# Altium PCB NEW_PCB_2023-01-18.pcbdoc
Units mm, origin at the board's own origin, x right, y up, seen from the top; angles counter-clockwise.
Board outline 66.65 x 67.28 mm, 2 copper layers (Top Layer, Bottom Layer); 6 components, 17 nets, 50 pads, 2 vias.
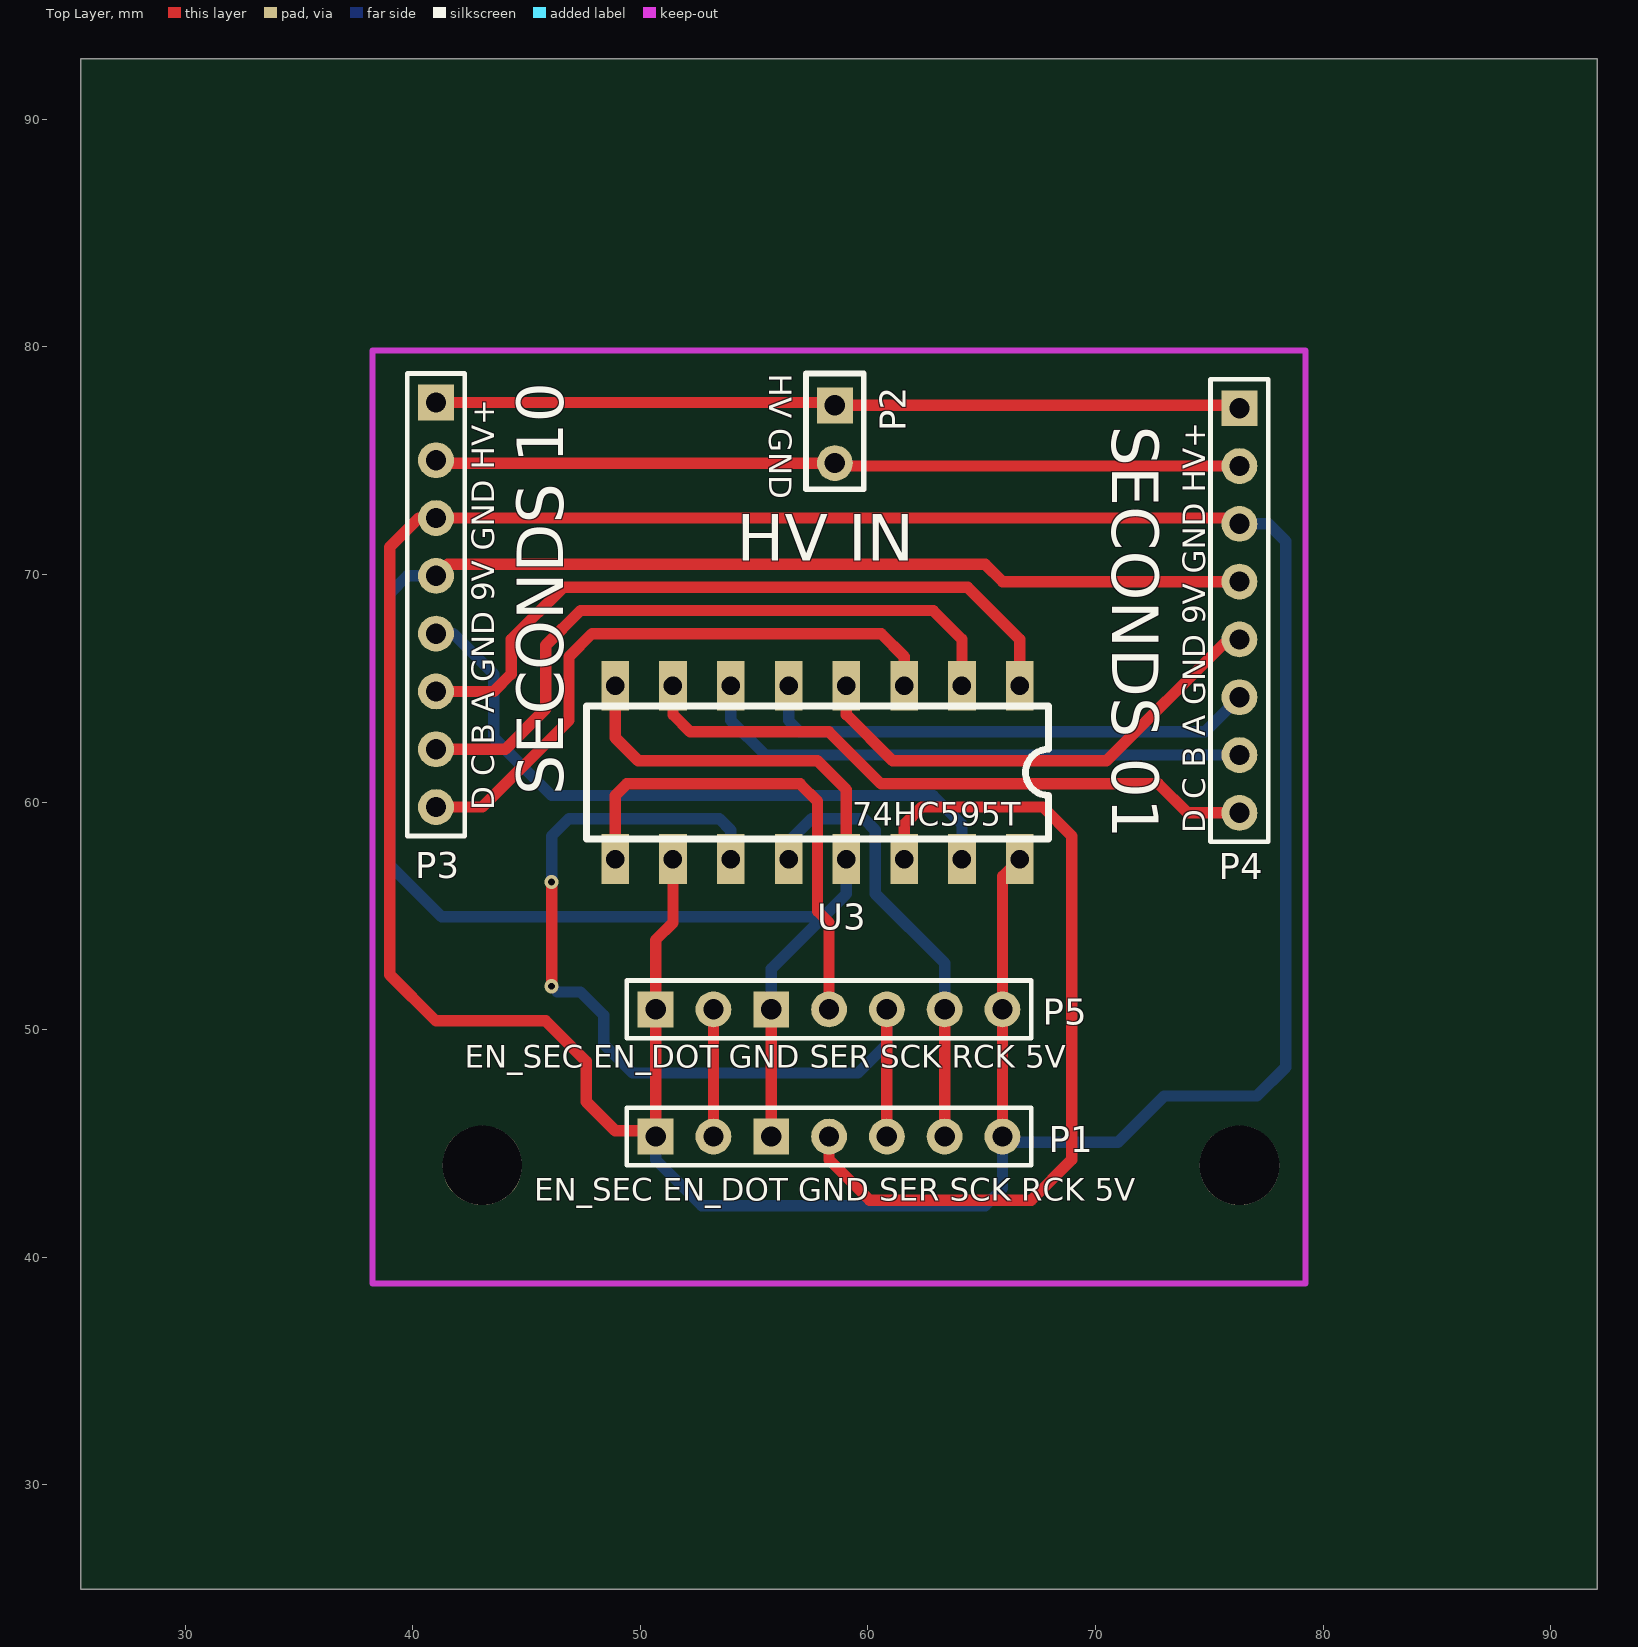
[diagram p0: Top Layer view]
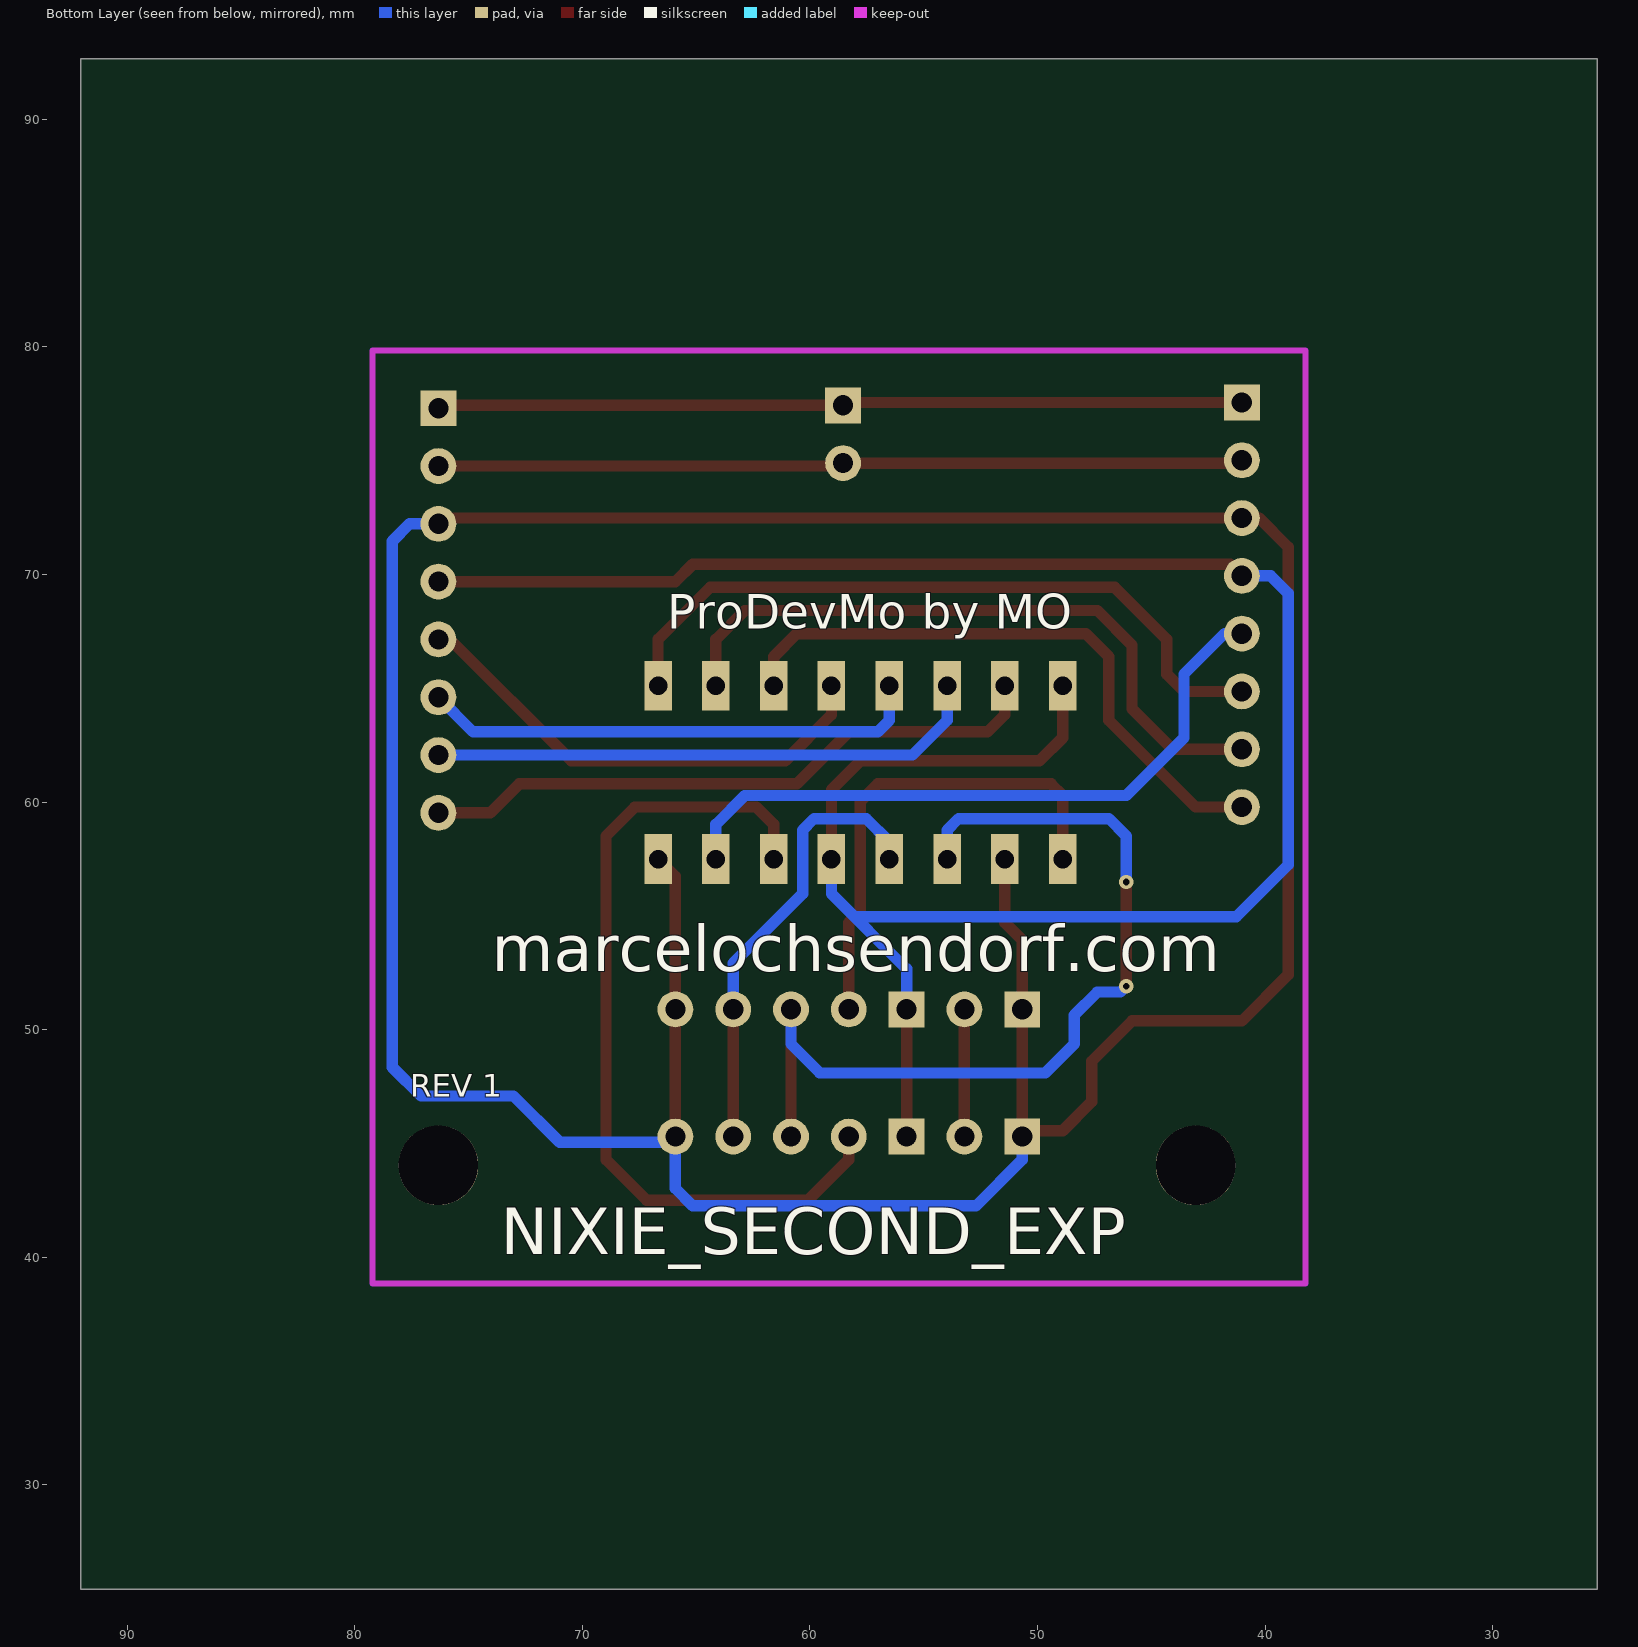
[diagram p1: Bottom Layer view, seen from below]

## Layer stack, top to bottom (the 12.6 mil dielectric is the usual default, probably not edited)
Top Layer: signal copper (thickness not stored)
Dielectric: dielectric 0.32, FR-4, Dk 4.8
Bottom Layer: signal copper (thickness not stored)

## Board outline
92.054,25.4 25.4,25.4 25.4,92.675 92.054,92.675

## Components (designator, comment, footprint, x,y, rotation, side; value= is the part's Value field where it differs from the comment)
P1 "Header2.54mm_1*7P" HDR-7X1/2.54 58.293,45.304 r0 top
P2 "Header-Female-2.54_1x2" HDR-2X1/2.54 57.277,78.832 r270 top
P3 "Header2.54mm 1*8P" HDR-8X1/2.54 41.021,69.942 r270 top
P4 "Header2.54mm 1*8P" HDR-8X1/2.54 76.327,69.688 r270 top
P5 "Header2.54mm_1*7P" HDR-7X1/2.54 58.293,50.892 r0 top
U3 "74HC595" DIL16 57.785,61.306 r180 top

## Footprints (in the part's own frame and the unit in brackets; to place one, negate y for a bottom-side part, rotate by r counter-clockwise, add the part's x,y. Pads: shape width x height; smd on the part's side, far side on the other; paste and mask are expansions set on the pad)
DIL16 [mil]
  rect 47.7x85.9 hole 32: 1(-350,-150) 2(-250,-150) 3(-150,-150) 4(-50,-150) 5(50,-150) 6(150,-150) 7(250,-150) 8(350,-150) 9(350,150) 10(250,150) 11(150,150) 12(50,150) 13(-50,150) 14(-150,150) 15(-250,150) 16(-350,150)
  silkscreen extent -400,-115 400,115
HDR-2X1/2.54 [mil]
  rect 62x62 hole 35: 1(55,50)
  round 62 hole 35: 2(155,50)
  silkscreen extent 0,0 200,100
HDR-7X1/2.54 [mil]
  rect 62x62 hole 35: 1(-300,0) 3(-100,0)
  round 62 hole 35: 2(-200,0) 4(0,0) 5(100,0) 6(200,0) 7(300,0)
  silkscreen extent -350,-50 350,50
HDR-8X1/2.54 [mil]
  rect 62x62 hole 35: 1(-300,0)
  round 62 hole 35: 2(-200,0) 3(-100,0) 4(0,0) 5(100,0) 6(200,0) 7(300,0) 8(400,0)
  silkscreen extent -350,-50 450,50

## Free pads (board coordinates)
  round 3.5 hole 3.5 unplated: ""(43.053,44.034) ""(76.327,44.034)

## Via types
v1: diameter 0.62, hole 0.305, Top Layer to Bottom Layer, tented both sides, 2 vias

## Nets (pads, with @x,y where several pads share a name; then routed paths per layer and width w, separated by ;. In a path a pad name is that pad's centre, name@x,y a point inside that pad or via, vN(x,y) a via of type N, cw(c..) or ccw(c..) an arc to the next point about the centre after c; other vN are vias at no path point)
+5V: P1.1 P1.7 P3.3 P4.3 P5.1 P5.7 U3.10 U3.16 | length 156.5
  Top Layer w0.5: U3.10 51.435,54.702 50.673,53.94 P5.1 P1.1 50.419,45.558 48.895,45.558 47.625,46.828 47.625,48.606 45.847,50.384 41.021,50.384 38.989,52.416 38.989,71.212 40.259,72.482 P3.3 76.073,72.482 P4.3 ; P1.7 P5.7 65.913,56.734 U3.16
  Bottom Layer w0.5: P1.1 50.673,44.288 52.705,42.256 65.151,42.256 65.913,43.018 P1.7 66.167,45.05 70.993,45.05 73.025,47.082 77.089,47.082 78.359,48.352 78.359,71.466 77.597,72.228 P4.3
GND: P1.3 P3.4 P4.4 P5.3 U3.8 U3.13 | length 101.6
  Top Layer w0.5: P3.4 41.529,70.45 65.151,70.45 65.913,69.688 P4.4 ; U3.8 48.895,62.83 49.911,61.814 57.785,61.814 59.055,60.544 U3.13 ; P1.3 P5.3
  Bottom Layer w0.5: P3.4 39.751,69.942 38.989,69.18 38.989,57.242 41.275,54.956 58.039,54.956 59.055,55.972 ; P5.3 55.753,52.67 59.055,55.972 ; U3.13 59.055,55.972
P1_2: P1.2 P5.2 | length 5.6
  Top Layer w0.5: P1.2 P5.2
P1_4: P1.4 U3.14 | length 37.1
  Top Layer w0.5: P1.4 58.293,44.288 60.071,42.51 67.183,42.51 68.961,44.288 68.961,58.512 67.691,59.782 62.357,59.782 61.595,59.02 U3.14
P1_5: P1.5 P5.5 U3.11 | length 41
  Top Layer w0.5: v1(46.101,51.908) v1(46.101,56.48) ; P1.5 P5.5
  Bottom Layer w0.5: v1(46.101,51.908) 46.355,51.654 47.371,51.654 48.387,50.638 48.387,49.368 49.657,48.098 59.563,48.098 60.833,49.368 P5.5 ; v1(46.101,56.48) 46.101,58.512 46.863,59.274 53.467,59.274 53.975,58.766 U3.11
P1_6: P1.6 P5.6 U3.12 | length 19.9
  Top Layer w0.5: P1.6 P5.6
  Bottom Layer w0.5: U3.12 56.515,58.258 57.531,59.274 59.817,59.274 60.325,58.766 60.325,55.972 63.373,52.924 P5.6
P2_1: P2.1 P3.1 P4.1 | length 35.4
  Top Layer w0.5: P3.1 58.42,77.562 P2.1 76.2,77.435 P4.1
P2_2: P2.2 P3.2 P4.2 | length 35.4
  Top Layer w0.5: P3.2 41.148,74.895 P2.2 58.674,74.768 P4.2
U3_1: P3.6 U3.1 | length 31.4
  Top Layer w0.5: P3.6 43.561,64.862 44.323,65.624 44.323,67.148 46.609,69.434 64.389,69.434 66.675,67.148 U3.1
U3_2: P3.7 U3.2 | length 29.8
  Top Layer w0.5: P3.7 44.069,62.322 45.847,64.1 45.847,66.894 47.371,68.418 62.865,68.418 64.135,67.148 U3.2
U3_3: P3.8 U3.3 | length 27.1
  Top Layer w0.5: P3.8 43.053,59.782 46.863,63.592 46.863,66.386 47.879,67.402 60.579,67.402 61.595,66.386 U3.3
U3_4: P4.5 U3.4 | length 21.6
  Top Layer w0.5: U3.4 59.055,63.846 61.087,61.814 70.485,61.814 75.819,67.148 P4.5
U3_5: P4.6 U3.5 | length 22.2
  Bottom Layer w0.5: U3.5 56.515,63.592 57.023,63.084 74.803,63.084 P4.6
U3_6: P4.7 U3.6 | length 24.5
  Bottom Layer w0.5: U3.6 53.975,63.592 55.499,62.068 P4.7
U3_7: P4.8 U3.7 | length 28
  Top Layer w0.5: U3.7 51.435,63.846 52.197,63.084 58.293,63.084 60.579,60.798 72.771,60.798 74.041,59.528 P4.8
U3_9: P5.4 U3.9 | length 21.6
  Top Layer w0.5: U3.9 48.895,60.29 49.403,60.798 57.023,60.798 57.785,60.036 57.785,55.21 58.293,54.702 P5.4
U3_15: P3.5 U3.15 | length 29.7
  Bottom Layer w0.5: P3.5 41.783,67.402 43.561,65.624 43.561,62.83 46.101,60.29 62.865,60.29 64.135,59.02 U3.15

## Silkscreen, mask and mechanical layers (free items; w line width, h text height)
Top Overlay:
  text "HV GND" at 55.662,78.832 h1 r270
  text "SECONDS 01" at 70.739,76.546 h2.03 r270
  text "HV IN" at 54.229,70.613 h2.03
  text "SECONDS 10" at 46.609,60.29 h2.03 r90
  text "D C B A GND 9V GND HV+" at 43.591,59.643 h1 r90
  text "74HC595T" at 59.309,58.957 h1.03
  text "D C B A GND 9V GND HV+" at 74.833,58.627 h1 r90
  text "EN_SEC EN_DOT GND SER SCK RCK 5V" at 42.291,48.322 h1
  text "EN_SEC EN_DOT GND SER SCK RCK 5V" at 45.339,42.48 h1
Bottom Overlay:
  text "ProDevMo by MO" at 66.278,67.612 h1.5
  text "marcelochsendorf.com" at 73.986,52.578 h2.03
  text "REV 1" at 77.569,47.053 h1
  text "NIXIE_SECOND_EXP" at 73.579,40.132 h2.03
Document:
  lines w0.003: 58.727,59.037 58.727,59.038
